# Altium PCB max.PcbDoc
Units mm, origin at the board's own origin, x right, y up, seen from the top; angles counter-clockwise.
Board outline 61 x 42 mm, 2 copper layers (Top Layer, Bottom Layer); 14 components, 20 nets, 110 pads, 35 vias.
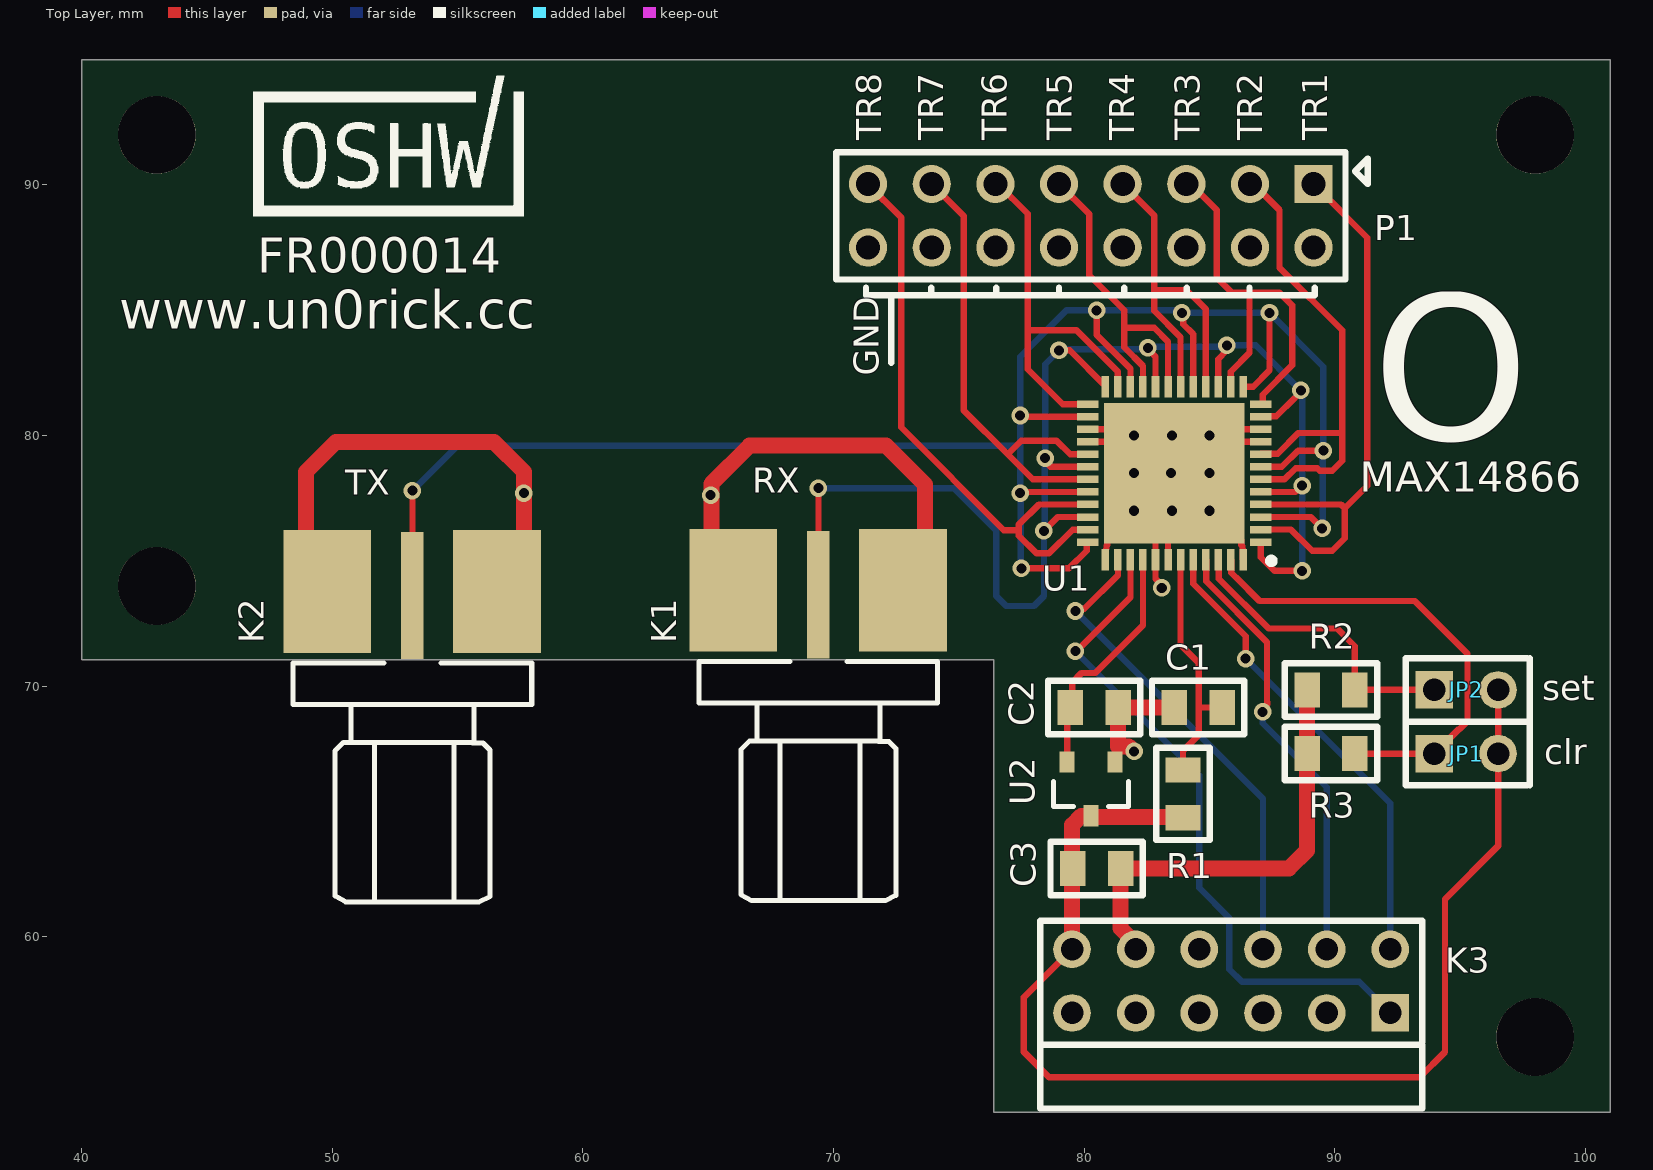
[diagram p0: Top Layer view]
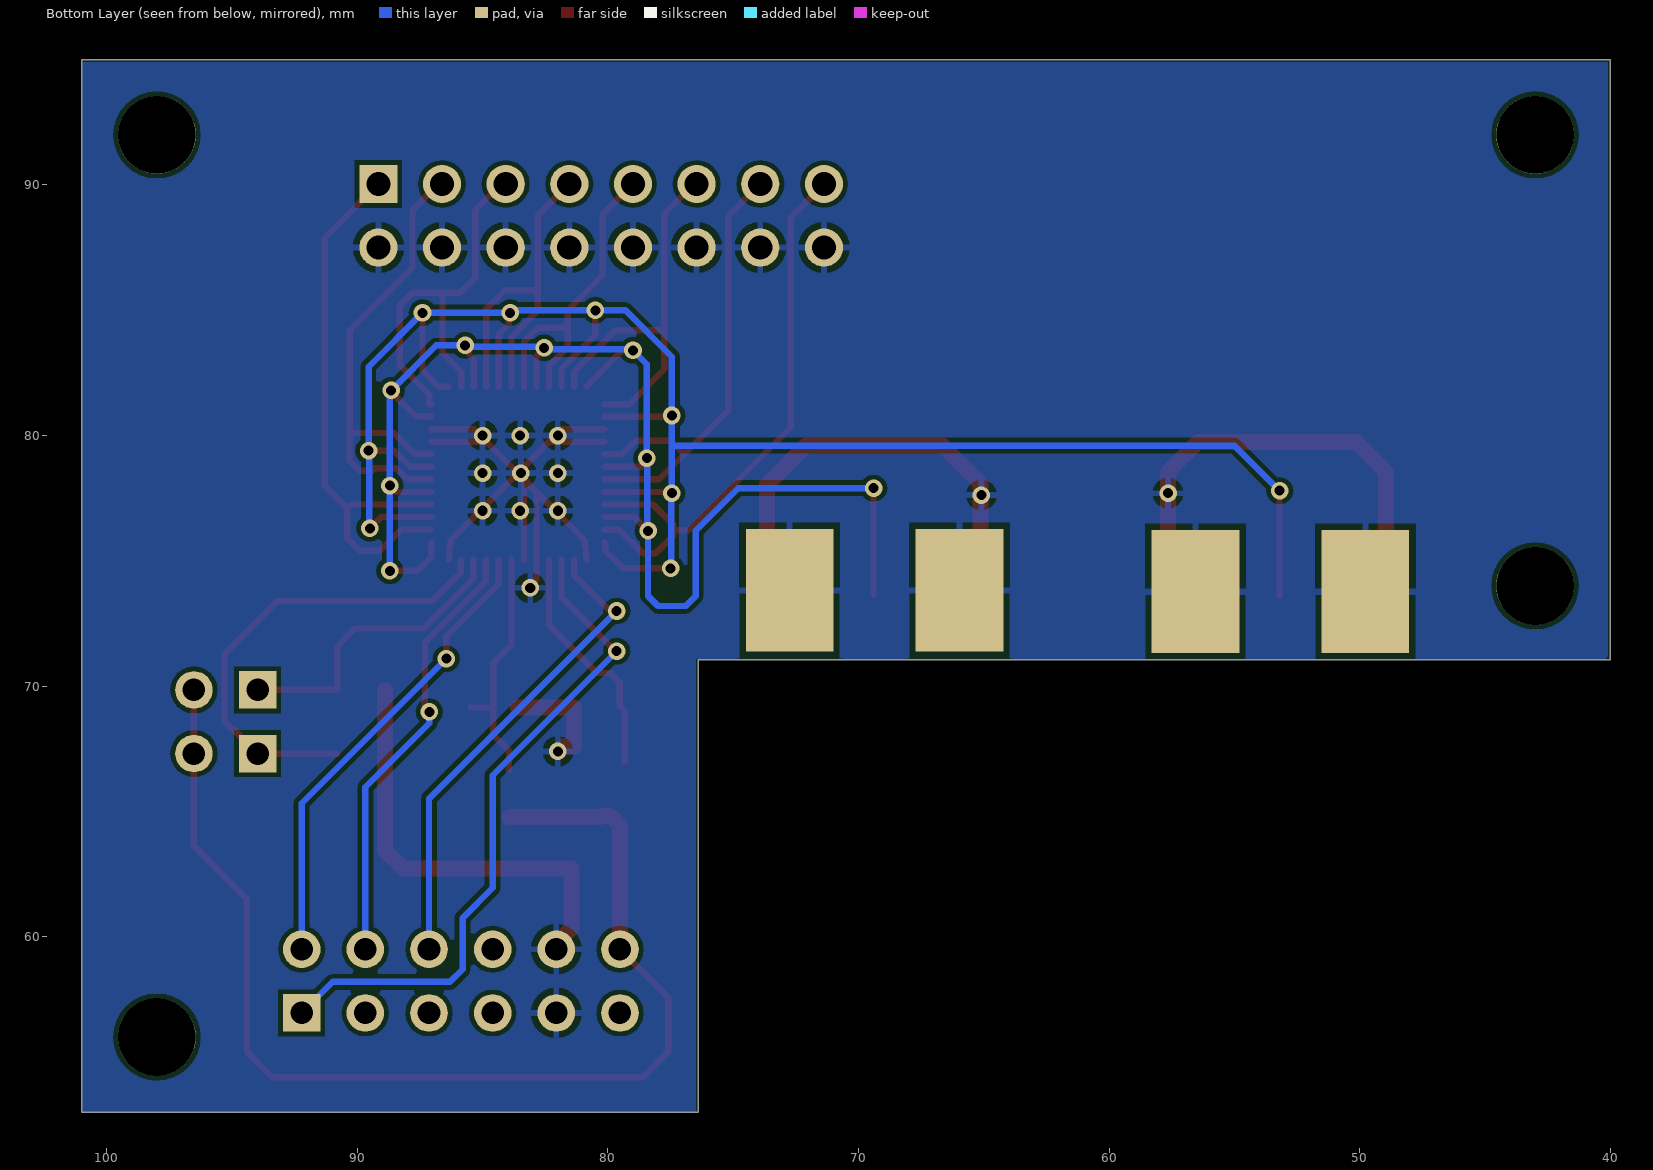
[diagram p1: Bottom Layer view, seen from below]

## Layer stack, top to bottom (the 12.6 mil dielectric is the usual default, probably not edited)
Top Solder: solder mask 0.0102, Solder Resist, Dk 3.5
Top Layer: signal copper 0.0356
Dielectric 1: dielectric 0.32, FR-4, Dk 4.8
Bottom Layer: signal copper 0.0356
Bottom Solder: solder mask 0.0102, Solder Resist, Dk 3.5

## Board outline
76.404,71.054 76.404,53 101,53 101,95 40,95 40,71.054

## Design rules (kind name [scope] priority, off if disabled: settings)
Clearance [All] p1: gap=0.178 ignorepadtopadclearanceinfootprint=TRUE
ComponentClearance [All] p1: gap=0 collisioncheckmode=3 verticalgap=0 showdistances=FALSE
HoleSize [All] p1: absolutevalues=TRUE maxlimit=3.81 minlimit=0.025 maxpercent=80.000 minpercent=20.000
MinimumSolderMaskSliver [All] p1: minsoldermaskwidth=0
PolygonConnect [All] p1: connectstyle=Relief reliefconductorwidth=0.254 reliefentries=4 polygonreliefangle="90 Angle" airgapwidth=0.254
RoutingVias [All] p1: holewidth=0.3 width=0.7 viastyle="Through Hole" minholewidth=0.3 minwidth=0.7 maxholewidth=0.3 maxwidth=0.7
SilkToSilkClearance [All] p1: silktosilkclearance=0.152
SilkToSolderMaskClearance [IsPad] p1: minsilkscreentomaskgap=0.102 clearancetoexposedcopper=TRUE
SolderMaskExpansion [All] p1: expansion=0.102 istentingtop=FALSE
Width [All] p1: maxlimit=2.54 minlimit=0.254 preferedwidth=0.254
25 further rules are at their usual default settings.

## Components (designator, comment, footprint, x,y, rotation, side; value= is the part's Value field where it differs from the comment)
C1 "cap0805" SM0805 85.505,69.15 r180 top value=0.1
C2 "cap0805" SM0805 79.45,69.15 r0 top value=1u
C3 "cap0805" SM0805 81.455,62.725 r180 top value=1u
JP1 "JUMPER2" JUMPER2 93.98,67.31 r90 top
JP2 "JUMPER2" JUMPER2 93.98,69.85 r90 top
K1 "SMA_MALE_FEMALE" "AMPHENOL_MALE _FEMALE" 69.4,72.25 r90 top
K2 "SMA_MALE_FEMALE" "AMPHENOL_MALE _FEMALE" 53.2,72.2 r90 top
K3 "PMOD_6x2_ra_male_mirrored" PMOD_6x2_RA_MALE_MIRRORED 79.52,59.5 r0 top
P1 "2x8, 2.54mm vertical" "2x8 pin 2.54mm" 89.16,90.04 r270 top
R1 "res0805_EU" SM0805 83.95,66.655 r270 top value=10
R2 "res0805_EU" SM0805 90.805,69.85 r180 top value=10k
R3 "res0805_EU" SM0805 90.805,67.31 r180 top value=10k
U1 "MAX14866UTM+" QFN50P700X700X80-49N 83.6,78.5 r180 top
U2 "XC6206" SOT-23 80.275,65.9 r270 top

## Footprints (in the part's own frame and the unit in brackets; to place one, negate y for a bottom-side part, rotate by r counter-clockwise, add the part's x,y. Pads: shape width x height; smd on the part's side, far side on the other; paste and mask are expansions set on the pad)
"2x8 pin 2.54mm" [mil] "2x8 pin 2.54mm"
  rect 60x60 hole 38: 1(0,0)
  round 60 hole 38: 2(100,0) 3(0,-100) 4(100,-100) 5(0,-200) 6(100,-200) 7(0,-300) 8(100,-300) 9(0,-400) 10(100,-400) 11(0,-500) 12(100,-500) 13(0,-600) 14(100,-600) 15(0,-700) 16(100,-700)
  silkscreen extent -50,-750 150,85
"AMPHENOL_MALE _FEMALE" [mm]
  rect 5.1x0.9 smd: 1(1.397,0)
  rect 4.9x3.5 smd: 2(1.575,3.4) 2(1.575,-3.375)
  rect 4.9x3.5 smd far side: 2(1.575,3.425) 2(1.575,-3.35)
  silkscreen extent -10.81,-4.76 -1.28,4.76, body extent -10.8,-4.76 3.48,4.76, height 4.08
JUMPER2 [mm]
  rect 1.5x1.5 hole 0.9: 1(0,0)
  round 1.5 hole 0.9: 2(0,-2.54)
  silkscreen extent -1.27,-3.81 1.27,1.14
PMOD_6x2_RA_MALE_MIRRORED [mm] "2.54 mm right angle 6x2 pins"
  rect 1.5x1.5 hole 0.9: 1(12.7,-2.54)
  round 1.5 hole 0.9: 2(10.16,-2.54) 3(7.62,-2.54) 4(5.08,-2.54) 5(2.54,-2.54) 6(0,-2.54) 7(12.7,0) 8(10.16,0) 9(7.62,0) 10(5.08,0) 11(2.54,0) 12(0,0)
  silkscreen extent -1.27,-6.35 13.97,1.14
QFN50P700X700X80-49N [mm]
  rect 0.85x0.3 smd: 1(-3.45,2.75) 2(-3.45,2.25) 3(-3.45,1.75) 4(-3.45,1.25) 5(-3.45,0.75) 6(-3.45,0.25) 7(-3.45,-0.25) 8(-3.45,-0.75) 9(-3.45,-1.25) 10(-3.45,-1.75) 11(-3.45,-2.25) 12(-3.45,-2.75) 25(3.45,-2.75) 26(3.45,-2.25) 27(3.45,-1.75) 28(3.45,-1.25) 29(3.45,-0.75) 30(3.45,-0.25) 31(3.45,0.25) 32(3.45,0.75) 33(3.45,1.25) 34(3.45,1.75) 35(3.45,2.25) 36(3.45,2.75)
  rect 0.3x0.85 smd: 13(-2.75,-3.45) 14(-2.25,-3.45) 15(-1.75,-3.45) 16(-1.25,-3.45) 17(-0.75,-3.45) 18(-0.25,-3.45) 19(0.25,-3.45) 20(0.75,-3.45) 21(1.25,-3.45) 22(1.75,-3.45) 23(2.25,-3.45) 24(2.75,-3.45) 37(2.75,3.45) 38(2.25,3.45) 39(1.75,3.45) 40(1.25,3.45) 41(0.75,3.45) 42(0.25,3.45) 43(-0.25,3.45) 44(-0.75,3.45) 45(-1.25,3.45) 46(-1.75,3.45) 47(-2.25,3.45) 48(-2.75,3.45)
  rect 5.6x5.6 smd: 49(0,0)
  silkscreen extent -4,3.38 -3.75,3.62, body extent -3.55,-3.55 3.55,3.55, height 0.8
SM0805 [mil]
  rect 40x55 smd: 1(0,0) 2(75,0)
  silkscreen extent -35,-42 110,42
SOT-23 [mm] "SOT23_L from misc devices"
  rect 0.85x0.6 smd: 1(-1.075,0.95) 2(-1.075,-0.95) 3(1.075,0)
  silkscreen extent -0.3,-1.5 0.7,1.5, body extent -0.7,-1.5 0.7,1.5, height 1.1

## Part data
C1 C2 C3: "Capacitor"
K3: "PMOD_6x2_right_angle"
P1: library part "2x8, 2.54mm, vertical", "Header, 16-Pin"
R1 R2 R3: "Resistor"
U1: "Integrated Circuit", Manufacturer_Name="Maxim Integrated", Mouser Part Number=700-MAX14866UTM+
U2: "SOT-23-3 ldo"

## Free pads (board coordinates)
  round 3.1 hole 3.1 unplated: 0(43,74) 0(43,92) 0(98,56) 0(98,92)

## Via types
v1: diameter 0.7, hole 0.4, Top Layer to Bottom Layer, 35 vias

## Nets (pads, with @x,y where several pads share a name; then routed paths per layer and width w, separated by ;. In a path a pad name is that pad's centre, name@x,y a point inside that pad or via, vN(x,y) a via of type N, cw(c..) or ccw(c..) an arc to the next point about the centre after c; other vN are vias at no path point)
+5V: C3.2 JP1.2 JP2.2 K3.12 R1.2 U2.3 | length 47.4
  Top Layer w0.254: K3.12 77.6,57.58 77.6,55.4 78.6,54.4 93.4,54.4 94.4,55.4 94.4,61.5 96.52,63.62 JP1.2 JP2.2
  Top Layer w0.635: K3.12 79.52,64.453 79.892,64.825 U2.3 80.275,64.805 80.293,64.788 83.912,64.788 R1.2
clk: K3.8 U1.45 | length 17.7
  Top Layer w0.254: U1.45 84.873,75.027 84.873,74.18 87.3,71.753 87.3,69.375 87.307,69.368 87.307,69.278 87.125,69.096 v1(87.125,68.975)
  Bottom Layer w0.254: v1(87.125,68.975) 87.125,68.525 89.68,65.97 K3.8
clr: JP1.1 R3.1 U1.47 | length 19
  Top Layer w0.254: U1.47 85.873,75.027 85.873,74.521 86.074,74.32 86.08,74.32 87,73.4 93.2,73.4 95.3,71.3 95.3,68.6 94.992,68.292 94.962,68.292 JP1.1 90.905,67.31 R3.1
din: K3.7 U1.44 | length 18.7
  Top Layer w0.254: U1.44 84.35,74.093 86.45,71.993 86.45,71.306 86.444,71.3 v1@86.4,71.3
  Bottom Layer w0.254: v1(86.45,71.1) 92.22,65.33 K3.7
dout: K3.1 U1.39 | length 26.9
  Top Layer w0.254: v1@79.7,71.4 80.4,72.1 81.85,73.55 U1.39
  Bottom Layer w0.254: v1(79.65,71.4) 84.6,66.45 84.6,61.95 85.8,60.75 85.8,58.7 86.3,58.2 90.98,58.2 K3.1
GND: C1.2 C2.2 C3.1 K1.2 K2.2 K3.5 K3.11 P1.2 P1.4 P1.6 P1.8 P1.10 P1.12 P1.14 P1.16 R2.2 R3.2 U1.9 U1.10 U1.27 U1.28 U1.37 U1.41 U1.42 U1.48 U1.49 U2.1 | length 89.1
  Top Layer w0.254: U1.28 U1.49@82.35,79.75 ; U1.27 81.85,80.25 U1.49@82.35,79.75 ; U1.37 80.873,75.073 80.873,75.467 80.895,75.489 80.895,75.601 80.927,75.633 80.927,75.827 U1.49@82.85,77.75 ; C2.2@81.16,68.959 C2.2@81.16,69.15 ; v1(83.1,73.925) 83.1,74.03 82.85,74.28 U1.41 U1.49@82.85,77.75 ; U1.42 U1.49@83.35,78.25 ; U1.48 86.327,75.073 86.327,75.467 86.32,75.474 86.32,75.586 86.273,75.633 86.273,75.827 U1.49 ; U1.9 U1.49@84.85,79.75 ; U1.10 85.35,80.25 U1.49@84.85,79.75 ; U1.49@82.35,79.75 83.475,78.625 v1(83.475,78.5) ; U1.49@82.85,77.75 U1.49@83.35,78.25 ; U1.49@83.35,78.25 83.475,78.375 v1(83.475,78.5) ; v1(83.475,78.5) U1.49 ; v1(83.475,78.5) U1.49 ; U1.49 U1.49@84.85,79.75
  Top Layer w0.635: K2.2@48.95,73.775 48.95,78.55 50.15,79.75 56.45,79.75 57.65,78.55 57.65,73.975 K2.2@57.45,73.775 ; K1.2@65.15,73.825 65.125,73.85 65.125,78.075 66.65,79.6 72.1,79.6 73.65,78.05 K1.2@73.65,73.825 ; v1@81.95,67.425 81.775,67.6 81.355,67.6 C2.2 C1.2 ; K3.11 82.06,59.734 81.455,60.339 C3.1 88.175,62.725 88.9,63.45 R3.2 R2.2
  other v1: 82,67.4 82,77 83.5,77 85,77 65.1,77.625 57.65,77.7 82,78.5 85,78.5 82,80 83.5,80 85,80
le: K3.9 U1.38 | length 19.5
  Top Layer w0.254: v1(79.65,73) 79.735,73.085 80.01,73.085 81.352,74.427 81.352,75.048 U1.38
  Bottom Layer w0.254: v1(79.65,73) 87.14,65.51 K3.9
NetC1_1: C1.1 R1.1 U1.43 | length 9.9
  Top Layer w0.254: U1.43 83.85,71.65 84.575,70.925 84.575,69.125 ; R1.1@83.975,66.68 R1.1 83.95,67.425 84.575,68.05 84.575,69.125 ; C1.1 84.6,69.15 84.575,69.125
NetC2_1: C2.1 U1.40 U2.2 | length 9.7
  Top Layer w0.254: U2.2 79.325,69.025 C2.1 79.525,69.225 79.525,70.15 79.9,70.525 80.45,70.525 82.35,72.425 U1.40
NetK1_1: K1.1 U1.1 U1.5 U1.11 U1.15 U1.20 U1.24 U1.30 U1.34 | length 60.2
  Top Layer w0.254: K1.1 v1(69.4,77.9) ; v1(78.4,76.2) 78.95,76.75 U1.34 ; v1@78.4,79 78.65,78.75 U1.30 ; v1(79,83.4) 79.427,83.4 80.85,81.977 U1.24 ; v1@82.6,83.4 82.85,83.15 U1.20 ; U1.15 85.35,83.05 85.7,83.4 v1(85.7,83.6) ; U1.1 87.05,75.15 87.6,74.6 v1(88.7,74.6) ; U1.5 88.429,77.75 88.679,78 v1(88.7,78) ; U1.11 87.073,80.773 87.673,80.773 88.4,81.5
  Bottom Layer w0.254: v1(69.4,77.9) 74.8,77.9 76.5,76.2 76.5,73.6 76.9,73.2 78,73.2 78.4,73.6 v1(78.4,76.2) 78.425,76.225 78.425,79.075 v1(78.45,79.1) 78.45,82.85 v1(79,83.4) 79.05,83.45 82.5,83.45 v1(82.55,83.5) 82.6,83.55 85.65,83.55 v1(85.7,83.6) 86.85,83.6 v1(88.65,81.8) 88.7,81.75 v1(88.7,78) 88.7,75.735 v1(88.7,74.6)
NetK2_1: K2.1 U1.3 U1.7 U1.13 U1.17 U1.22 U1.26 U1.32 U1.36 | length 82.4
  Top Layer w0.254: K2.1 v1(53.2,77.8) ; v1@77.4,77.7 77.45,77.75 U1.32 ; v1(77.5,74.7) 79.4,74.7 80.1,75.4 80.1,75.727 80.123,75.75 U1.36 ; v1@77.5,80.8 77.55,80.75 U1.26 ; v1(80.5,85) 80.5,84.013 81.85,82.663 U1.22 ; v1@83.8,84.8 83.857,84.8 83.963,84.694 83.963,84.437 84.35,84.05 U1.17 ; U1.13 86.75,81.95 87.4,82.6 v1(87.4,84.9) ; U1.3 89.05,76.75 v1(89.5,76.3) ; U1.7 87.053,78.753 87.892,78.753 88.539,79.4 v1@89.5,79.4
  Bottom Layer w0.254: v1(53.2,77.8) 55,79.6 77.45,79.6 ; v1(77.5,74.7) 77.475,74.725 77.475,77.675 v1(77.45,77.7) 77.45,79.6 ; v1(89.5,76.3) 89.525,76.325 89.525,79.375 v1(89.55,79.4) 89.55,82.75 v1(87.4,84.9) v1(83.9,84.9) 83.779,84.9 83.679,85 v1(80.5,85) 79.3,85 77.45,83.15 v1(77.45,80.8) 77.45,79.6
set: JP2.1 R2.1 U1.46 | length 12.2
  Top Layer w0.254: U1.46 85.373,75.027 85.373,74.291 87.364,72.3 90.1,72.3 90.805,71.595 R2.1 JP2.1
tr1: P1.1 U1.2 U1.4 | length 22.7
  Top Layer w0.254: U1.2 88.25,76.25 89.1,75.4 89.9,75.4 90.4,75.9 90.4,77.1 ; U1.4 90.25,77.25 90.4,77.1 ; P1.1 91.3,87.9 91.3,78 90.4,77.1
tr2: P1.3 U1.6 U1.8 | length 19.9
  Top Layer w0.254: P1.3 86.76,90.04 87.8,89 87.8,86.7 90.3,84.2 90.3,80.1 ; U1.6 88,78.25 88.45,78.7 89.3,78.7 89.4,78.6 89.9,78.6 90.3,79 90.3,80.1 ; U1.8 87.073,79.273 87.723,79.273 88.55,80.1 90.3,80.1
tr3: P1.5 U1.12 U1.14 | length 16.4
  Top Layer w0.254: P1.5 84.26,90.04 85.3,89 85.3,86.3 85.9,85.7 86.6,85.7 ; U1.14 85.853,81.953 85.853,82.553 86.6,83.3 86.6,85.7 ; U1.12 87.109,81.25 87.132,81.273 87.132,81.632 88.3,82.8 88.3,85.2 87.8,85.7 86.6,85.7
tr4: P1.7 U1.16 U1.18 | length 14.5
  Top Layer w0.254: P1.7 82.8,88.78 82.8,85.9 ; U1.18 83.85,83.925 82.8,84.975 82.8,85.8 82.8,85.9 ; U1.16 84.85,85.05 84.1,85.8 82.9,85.8 82.8,85.9
tr5: P1.9 U1.19 U1.21 | length 13.3
  Top Layer w0.254: P1.9 80.2,88.84 80.2,86.4 81.6,85 81.6,84.3 ; U1.21 82.35,82.774 81.6,83.524 81.6,84.3 ; U1.19 83.35,83.75 82.8,84.3 81.6,84.3
tr6: P1.11 U1.23 U1.25 | length 15.8
  Top Layer w0.254: P1.11 76.56,90.04 77.75,88.85 77.75,84.2 ; U1.25 79.15,81.25 77.75,82.65 77.75,84.2 ; U1.23 81.342,81.958 81.342,82.558 79.7,84.2 77.75,84.2
tr7: P1.13 U1.29 U1.31 | length 19.3
  Top Layer w0.254: P1.13 75.2,88.76 75.2,81 76.95,79.25 ; U1.31 77.95,78.25 76.95,79.25 ; U1.29 79.45,79.25 78.9,79.8 77.5,79.8 76.95,79.25
tr8: P1.15 U1.33 U1.35 | length 23.6
  Top Layer w0.254: P1.15 71.38,90.02 72.7,88.7 72.7,80.325 76.8,76.225 77.4,76.225 ; U1.35 80.147,76.247 79.547,76.247 78.6,75.3 78.1,75.3 77.4,76 77.4,76.225 ; U1.33 78.2,77.25 77.4,76.45 77.4,76.225
pads on no net: K3.2 K3.3 K3.4 K3.6 K3.10

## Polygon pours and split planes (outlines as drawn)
GND on Bottom Layer "GND_L02_P000" (solid, pour order 0): 40.1,94.9 40.1,71.2 40.2,71.1 76.5,71.1 76.5,53 101,53 101,94.9

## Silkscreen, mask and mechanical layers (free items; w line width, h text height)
Top Overlay:
  drawing of 16 lines, arcs and shapes, not listed
  text "TR8" at 71.91,91.79 h1 r90
  text "TR6" at 76.91,91.79 h1 r90
  text "TR5" at 79.51,91.79 h1 r90
  text "TR4" at 82.01,91.79 h1 r90
  text "TR3" at 84.61,91.79 h1 r90
  text "TR2" at 87.11,91.79 h1 r90
  text "TR1" at 89.71,91.79 h1 r90
  text "TR7" at 74.383,91.779 h1 r90
  text "FR000014" at 47.004,86.504 h1.4
  text "www.un0rick.cc" at 41.504,84.254 h1.52
  text "GND" at 71.81,82.39 h1 r90
  text "MAX14866" at 91,77.75 h1.2
  text "RX" at 66.765,77.715 h1
  text "TX" at 50.515,77.64 h1
  text "O" at 91.5,77 h15
  text "set" at 98.29,69.44 h1
  text "clr" at 98.365,66.89 h1
Mechanical 1:
  lines w0.254: 40,71 76.4,71 76.4,53 101,53 101,95 40,95 40,71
